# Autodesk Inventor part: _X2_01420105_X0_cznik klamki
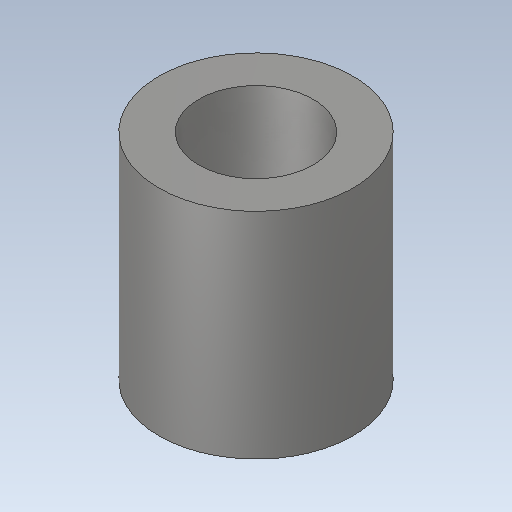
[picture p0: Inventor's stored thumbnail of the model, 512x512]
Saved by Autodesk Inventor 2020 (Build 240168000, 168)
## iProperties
Created: 2015-11
Part Number: _X2_01420105_X0_cznik klamki
Material: Ogólny
Document SubType Name: Modeling
Designer: Tomasz
Density: 1 g/cm^3
Appearance: Domyślna
Sending System: SolidWorks 2017
Last Author: Tomasz
Last Saved: 2017-11-19
Author: Tomasz
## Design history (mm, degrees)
feature "Imported1"
node "Bryła1"
